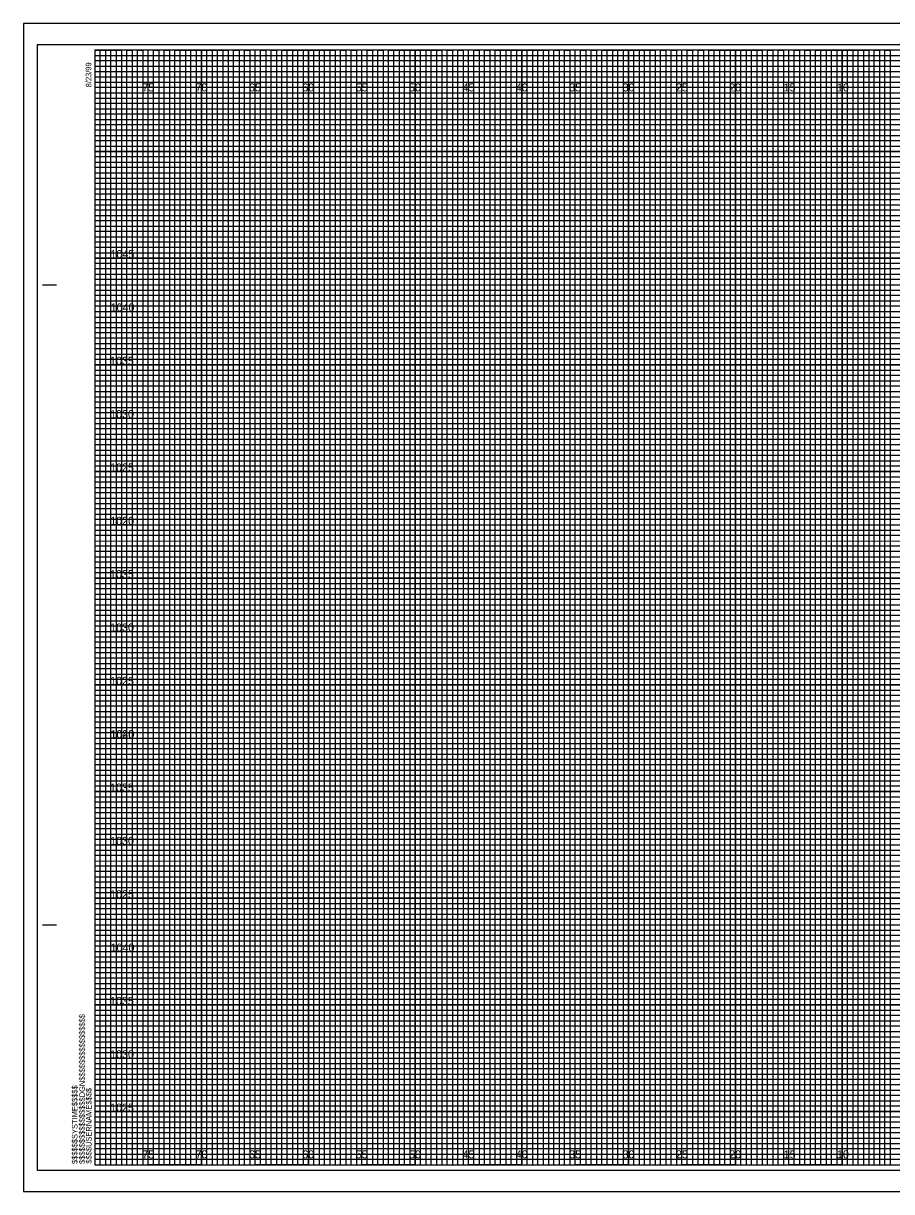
# Model space of a CAD drawing. Extents: x -7 to 162, y -2 to 987.
# Drawn here: x -6.7 to 74.6, y -2.5 to 107 of the extents above; entities that cross this region are included whole.
import ezdxf

# ---------------------------------------------------------------- set-up
doc = ezdxf.new("R2010")
doc.units = 0
for name, color, linetype in [('Exist Cross Section Cell', 7, 'Continuous'), ('Exist XS Center Line Elevation Label', 7, 'Continuous'), ('Exist XS Ground Line', 7, 'Continuous'), ('Prop CMT Concrete Structures', 7, 'Continuous'), ('Prop CMT Guardrail Widen Shoulder', 7, 'Continuous'), ('Prop CMT Pvmt Course 1', 7, 'Continuous'), ('Prop CMT Pvmt Surface', 7, 'Continuous'), ('Prop CMT Shld Paved Course 1', 7, 'Continuous'), ('Prop CMT Slope Grass', 7, 'Continuous'), ('Prop CMT Subgrade Earthwork', 7, 'Continuous'), ('Typical Text Label CELL', 7, 'Continuous')]:
    doc.layers.add(name, color=color, linetype=linetype)

msp = doc.modelspace()

# ---------------------------------------------------------------- linework, layer by layer
at = {"layer": 'Exist XS Center Line Elevation Label'}
for points in [[(0, 104.5), (2.5, 104.5), (2.5, 0), (7.5, 0), (7.5, 104.5), (12.5, 104.5), (12.5, 0), (17.5, 0), (17.5, 104.5), (22.5, 104.5), (22.5, 0), (27.5, 0), (27.5, 104.5), (32.5, 104.5), (32.5, 0), (37.5, 0), (37.5, 104.5), (42.5, 104.5), (42.5, 0), (47.5, 0), (47.5, 104.5), (52.5, 104.5), (52.5, 0), (57.5, 0), (57.5, 104.5), (62.5, 104.5), (62.5, 0), (67.5, 0), (67.5, 104.5), (72.5, 104.5), (72.5, 0), (77.5, 0)], [(0, 102), (137.5, 102)], [(0, 92.5), (160, 92.5), (160, 97.5), (0, 97.5)], [(0, 82.5), (160, 82.5), (160, 87.5), (0, 87.5)], [(0, 72.5), (160, 72.5), (160, 77.5), (0, 77.5)], [(0, 62.5), (160, 62.5), (160, 67.5), (0, 67.5)], [(0, 52.5), (160, 52.5), (160, 57.5), (0, 57.5)], [(0, 42.5), (160, 42.5), (160, 47.5), (0, 47.5)], [(0, 32.5), (160, 32.5), (160, 37.5), (0, 37.5)], [(0, 22.5), (160, 22.5), (160, 27.5), (0, 27.5)], [(0, 12.5), (160, 12.5), (160, 17.5), (0, 17.5)], [(0, 2.5), (160, 2.5), (160, 7.5), (0, 7.5)]]:
    msp.add_lwpolyline(points, dxfattribs=at)
at = {"layer": 'Exist XS Ground Line'}
for p, q in [((5, 104.5), (0, 104.5)), ((5, 0), (5, 104.5)), ((15, 104.5), (10, 104.5)), ((10, 104.5), (10, 0)), ((15, 0), (15, 104.5)), ((25, 104.5), (20, 104.5)), ((20, 104.5), (20, 0)), ((25, 0), (25, 104.5)), ((35, 104.5), (30, 104.5)), ((30, 104.5), (30, 0)), ((35, 0), (35, 104.5)), ((45, 104.5), (40, 104.5)), ((40, 104.5), (40, 0)), ((45, 0), (45, 104.5)), ((55, 104.5), (50, 104.5)), ((50, 104.5), (50, 0)), ((55, 0), (55, 104.5)), ((65, 104.5), (60, 104.5)), ((60, 104.5), (60, 0)), ((65, 0), (65, 104.5)), ((75, 104.5), (70, 104.5)), ((70, 104.5), (70, 0)), ((10, 0), (5, 0)), ((20, 0), (15, 0)), ((30, 0), (25, 0)), ((40, 0), (35, 0)), ((50, 0), (45, 0)), ((60, 0), (55, 0)), ((70, 0), (65, 0))]:
    msp.add_line(p, q, dxfattribs=at)
for points in [[(0, 100), (160, 100), (160, 95), (0, 95)], [(0, 90), (160, 90), (160, 85), (0, 85)], [(0, 80), (160, 80), (160, 75), (0, 75)], [(0, 70), (160, 70), (160, 65), (0, 65)], [(0, 60), (160, 60), (160, 55), (0, 55)], [(0, 50), (160, 50), (160, 45), (0, 45)], [(0, 40), (160, 40), (160, 35), (0, 35)], [(0, 30), (160, 30), (160, 25), (0, 25)], [(0, 20), (160, 20), (160, 15), (0, 15)], [(0, 10), (160, 10), (160, 5), (0, 5)]]:
    msp.add_lwpolyline(points, dxfattribs=at)
at = {"layer": 'Prop CMT Concrete Structures'}
for p, q in [((5, 0), (5, 104.5)), ((10, 0), (10, 104.5)), ((15, 0), (15, 104.5)), ((20, 0), (20, 104.5)), ((25, 0), (25, 104.5)), ((30, 0), (30, 104.5)), ((35, 0), (35, 104.5)), ((40, 0), (40, 104.5)), ((45, 0), (45, 104.5)), ((50, 0), (50, 104.5)), ((55, 0), (55, 104.5)), ((60, 0), (60, 104.5)), ((65, 0), (65, 104.5)), ((70, 0), (70, 104.5)), ((0, 100), (160, 100)), ((0, 95), (160, 95)), ((0, 90), (160, 90)), ((0, 85), (160, 85)), ((0, 80), (160, 80)), ((0, 75), (160, 75)), ((0, 70), (160, 70)), ((0, 65), (160, 65)), ((0, 60), (160, 60)), ((0, 55), (160, 55)), ((0, 50), (160, 50)), ((0, 45), (160, 45)), ((0, 40), (160, 40)), ((0, 35), (160, 35)), ((0, 30), (160, 30)), ((0, 25), (160, 25)), ((0, 20), (160, 20)), ((0, 15), (160, 15)), ((0, 10), (160, 10)), ((0, 5), (160, 5))]:
    msp.add_line(p, q, dxfattribs=at)
at = {"layer": 'Prop CMT Guardrail Widen Shoulder'}
for p, q in [((161.65, 107), (-6.7, 107)), ((-6.7, 107), (-6.7, -2.5)), ((-6.7, -2.5), (161.65, -2.5))]:
    msp.add_line(p, q, dxfattribs=at)
at = {"layer": 'Prop CMT Pvmt Course 1'}
msp.add_lwpolyline([(-6.7, -2.5), (161.65, -2.5), (161.65, 107), (-6.7, 107)], close=True, dxfattribs=at)
at = {"layer": 'Prop CMT Pvmt Surface'}
for points in [[(0, 0), (0.5, 0), (0.5, 104.5), (1, 104.5), (1, 0)], [(1, 0), (1.5, 0), (1.5, 104.5), (2, 104.5), (2, 0)], [(2.5, 0), (3, 0), (3, 104.5), (3.5, 104.5), (3.5, 0)], [(3.5, 0), (4, 0), (4, 104.5), (4.5, 104.5), (4.5, 0)], [(5, 0), (5.5, 0), (5.5, 104.5), (6, 104.5), (6, 0)], [(6, 0), (6.5, 0), (6.5, 104.5), (7, 104.5), (7, 0)], [(7.5, 0), (8, 0), (8, 104.5), (8.5, 104.5), (8.5, 0)], [(8.5, 0), (9, 0), (9, 104.5), (9.5, 104.5), (9.5, 0)], [(10, 0), (10.5, 0), (10.5, 104.5), (11, 104.5), (11, 0)], [(11, 0), (11.5, 0), (11.5, 104.5), (12, 104.5), (12, 0)], [(12.5, 0), (13, 0), (13, 104.5), (13.5, 104.5), (13.5, 0)], [(13.5, 0), (14, 0), (14, 104.5), (14.5, 104.5), (14.5, 0)], [(15, 0), (15.5, 0), (15.5, 104.5), (16, 104.5), (16, 0)], [(16, 0), (16.5, 0), (16.5, 104.5), (17, 104.5), (17, 0)], [(17.5, 0), (18, 0), (18, 104.5), (18.5, 104.5), (18.5, 0)], [(18.5, 0), (19, 0), (19, 104.5), (19.5, 104.5), (19.5, 0)], [(20, 0), (20.5, 0), (20.5, 104.5), (21, 104.5), (21, 0)], [(21, 0), (21.5, 0), (21.5, 104.5), (22, 104.5), (22, 0)], [(22.5, 0), (23, 0), (23, 104.5), (23.5, 104.5), (23.5, 0)], [(23.5, 0), (24, 0), (24, 104.5), (24.5, 104.5), (24.5, 0)], [(25, 0), (25.5, 0), (25.5, 104.5), (26, 104.5), (26, 0)], [(26, 0), (26.5, 0), (26.5, 104.5), (27, 104.5), (27, 0)], [(27.5, 0), (28, 0), (28, 104.5), (28.5, 104.5), (28.5, 0)], [(28.5, 0), (29, 0), (29, 104.5), (29.5, 104.5), (29.5, 0)], [(30, 0), (30.5, 0), (30.5, 104.5), (31, 104.5), (31, 0)], [(31, 0), (31.5, 0), (31.5, 104.5), (32, 104.5), (32, 0)], [(32.5, 0), (33, 0), (33, 104.5), (33.5, 104.5), (33.5, 0)], [(33.5, 0), (34, 0), (34, 104.5), (34.5, 104.5), (34.5, 0)], [(35, 0), (35.5, 0), (35.5, 104.5), (36, 104.5), (36, 0)], [(36, 0), (36.5, 0), (36.5, 104.5), (37, 104.5), (37, 0)], [(37.5, 0), (38, 0), (38, 104.5), (38.5, 104.5), (38.5, 0)], [(38.5, 0), (39, 0), (39, 104.5), (39.5, 104.5), (39.5, 0)], [(40, 0), (40.5, 0), (40.5, 104.5), (41, 104.5), (41, 0)], [(41, 0), (41.5, 0), (41.5, 104.5), (42, 104.5), (42, 0)], [(42.5, 0), (43, 0), (43, 104.5), (43.5, 104.5), (43.5, 0)], [(43.5, 0), (44, 0), (44, 104.5), (44.5, 104.5), (44.5, 0)], [(45, 0), (45.5, 0), (45.5, 104.5), (46, 104.5), (46, 0)], [(46, 0), (46.5, 0), (46.5, 104.5), (47, 104.5), (47, 0)], [(47.5, 0), (48, 0), (48, 104.5), (48.5, 104.5), (48.5, 0)], [(48.5, 0), (49, 0), (49, 104.5), (49.5, 104.5), (49.5, 0)], [(50, 0), (50.5, 0), (50.5, 104.5), (51, 104.5), (51, 0)], [(51, 0), (51.5, 0), (51.5, 104.5), (52, 104.5), (52, 0)], [(52.5, 0), (53, 0), (53, 104.5), (53.5, 104.5), (53.5, 0)], [(53.5, 0), (54, 0), (54, 104.5), (54.5, 104.5), (54.5, 0)], [(55, 0), (55.5, 0), (55.5, 104.5), (56, 104.5), (56, 0)], [(56, 0), (56.5, 0), (56.5, 104.5), (57, 104.5), (57, 0)], [(57.5, 0), (58, 0), (58, 104.5), (58.5, 104.5), (58.5, 0)], [(58.5, 0), (59, 0), (59, 104.5), (59.5, 104.5), (59.5, 0)], [(60, 0), (60.5, 0), (60.5, 104.5), (61, 104.5), (61, 0)], [(61, 0), (61.5, 0), (61.5, 104.5), (62, 104.5), (62, 0)], [(62.5, 0), (63, 0), (63, 104.5), (63.5, 104.5), (63.5, 0)], [(63.5, 0), (64, 0), (64, 104.5), (64.5, 104.5), (64.5, 0)], [(65, 0), (65.5, 0), (65.5, 104.5), (66, 104.5), (66, 0)], [(66, 0), (66.5, 0), (66.5, 104.5), (67, 104.5), (67, 0)], [(67.5, 0), (68, 0), (68, 104.5), (68.5, 104.5), (68.5, 0)], [(68.5, 0), (69, 0), (69, 104.5), (69.5, 104.5), (69.5, 0)], [(70, 0), (70.5, 0), (70.5, 104.5), (71, 104.5), (71, 0)], [(71, 0), (71.5, 0), (71.5, 104.5), (72, 104.5), (72, 0)], [(72.5, 0), (73, 0), (73, 104.5), (73.5, 104.5), (73.5, 0)], [(73.5, 0), (74, 0), (74, 104.5), (74.5, 104.5), (74.5, 0)]]:
    msp.add_lwpolyline(points, dxfattribs=at)
at = {"layer": 'Prop CMT Shld Paved Course 1'}
for p, q in [((0, 104), (130, 104)), ((130, 103.49), (0, 103.49)), ((0, 103.49), (0, 103)), ((0, 103), (130, 103)), ((130, 102.45), (0, 102.45)), ((0, 102.45), (0, 102)), ((0, 102), (160, 102))]:
    msp.add_line(p, q, dxfattribs=at)
for points in [[(0, 101.5), (135, 101.5), (160, 101.5), (160, 101), (0, 101)], [(0, 100.5), (160, 100.5), (160, 99.5), (0, 99.5)], [(0, 99), (160, 99), (160, 98.5), (0, 98.49)], [(0, 98), (160, 98), (160, 97), (0, 97)], [(0, 96.5), (160, 96.5), (160, 96), (0, 96)], [(0, 95.5), (160, 95.5), (160, 94.5), (0, 94.5)], [(0, 94), (160, 94), (160, 93.5), (0, 93.5)], [(0, 93), (160, 93), (160, 92), (0, 92)], [(0, 91.5), (160, 91.5), (160, 91), (0, 91)], [(0, 90.5), (160, 90.5), (160, 89.5), (0, 89.5)], [(0, 89), (160, 89), (160, 88.5), (0, 88.5)], [(0, 88), (160, 88), (160, 86.98), (160, 86.5), (160, 86), (0, 86)], [(0, 87), (160, 87), (160, 86.5), (0, 86.5)], [(0, 85.5), (160, 85.5), (160, 84.5), (0, 84.52)], [(0, 84.52), (160, 84.5), (160, 84), (0, 84)], [(0, 83.5), (160, 83.5), (160, 83), (0, 83)], [(0, 82), (160, 82), (160, 81.5), (0, 81.5)], [(0, 81), (160, 81), (160, 80.5), (0, 80.5)], [(-0.04, 79.45), (160, 79.45), (160, 78.94), (-0.04, 78.94)], [(0, 78.5), (160, 78.5), (160, 78), (0, 78)], [(0, 77), (160, 77), (160, 76.5), (0, 76.5)], [(0, 76), (160, 76), (160, 75.5), (0, 75.5)], [(0, 74.5), (160, 74.5), (160, 74), (0, 74)], [(0, 73.5), (160, 73.5), (160, 73), (0, 73)], [(0, 72), (160, 72), (160, 71.5), (0, 71.5)], [(0, 71), (160, 71), (160, 70.5), (0, 70.5)], [(0, 69.5), (160, 69.5), (160, 68.99), (0, 69)], [(0, 68.5), (160, 68.5), (160, 68), (0, 68)], [(0, 67), (160, 67), (160, 66.5), (0, 66.5)], [(0, 66), (160, 66), (160, 65.5), (0, 65.5)], [(0, 64.5), (160, 64.5), (160, 64), (0, 64)], [(0, 63.5), (160, 63.5), (160, 63), (0, 63)], [(0, 62), (160, 62), (160, 61.5), (0, 61.5)], [(0, 61), (160, 61), (160, 60.5), (0, 60.5)], [(0, 59.5), (160, 59.5), (160, 59), (0, 59)], [(0, 58.5), (160.03, 58.45), (160, 58), (0, 58)], [(0, 57), (160, 57), (160, 56.5), (0, 56.5)], [(0, 56), (160, 56), (160, 55.5), (0, 55.5)], [(0, 54.5), (160, 54.5), (160, 54), (0, 54)], [(0, 53.5), (160, 53.5), (160, 53), (0, 53)], [(0, 52), (160, 52), (160, 51.5), (0, 51.5)], [(0, 51), (160, 51), (160, 50.5), (0, 50.5)], [(0, 49.5), (160, 49.5), (160, 49), (0, 49)], [(0, 48.5), (160, 48.5), (160, 48), (0, 48)], [(0, 47), (160, 47), (160, 46.5), (0, 46.5)], [(0, 46), (160, 46), (160, 45.5), (0, 45.5)], [(0, 44.5), (160, 44.5), (160, 44), (0, 44)], [(0, 43.5), (160, 43.5), (160, 43), (0, 43)], [(0, 42), (160, 42), (160, 41.5), (0, 41.5)], [(0, 41), (160, 41), (160, 40.5), (0, 40.5)], [(0, 39.5), (160, 39.5), (160, 38.99), (0, 39)], [(0, 38.5), (160, 38.5), (160, 38), (0, 38)], [(0, 37), (160, 37), (160, 36.5), (0, 36.5)], [(0, 36), (160, 36), (160, 35.5), (0, 35.5)], [(0, 34.5), (160, 34.5), (160, 34), (0, 34)], [(0, 33.5), (160, 33.5), (160, 33), (0, 33)], [(0, 32), (160, 32), (160, 31.5), (0, 31.5)], [(0, 31), (160, 31), (160, 30.5), (0, 30.5)], [(0, 29.5), (160, 29.5), (160, 29), (0, 29)], [(0, 28.5), (160.03, 28.46), (160, 28), (0, 28)], [(0, 27), (160, 27), (160, 26.5), (0, 26.5)], [(0, 26), (160, 26), (160, 25.5), (0, 25.5)], [(0, 24.5), (160, 24.5), (160, 24), (0, 24)], [(0, 23.5), (160, 23.5), (160, 23), (0, 23)], [(0, 22), (160, 22), (160, 21.5), (0, 21.5)], [(0, 21), (160, 21), (160, 20.5), (0, 20.5)], [(0, 19.5), (160, 19.5), (160, 19), (0, 19)], [(0, 18.5), (160, 18.5), (160, 18), (0, 18)], [(0, 17), (160, 17), (160, 16.5), (0, 16.5)], [(0, 16), (160, 16), (160, 15.5), (0, 15.5)], [(0, 14.5), (160, 14.5), (160, 14), (0, 14)], [(0, 13.5), (160, 13.5), (160, 13), (0, 13)], [(0, 12), (160, 12), (160, 11.5), (0, 11.5)], [(0, 11), (160, 11), (160, 10.5), (0, 10.5)], [(0, 9.5), (160, 9.5), (160, 9), (0, 9)], [(0, 8.5), (160, 8.5), (160, 8), (0, 8)], [(0, 7), (160, 7), (160, 6.5), (0, 6.5)], [(0, 6), (160, 6), (160, 5.5), (0, 5.5)], [(0, 4.5), (160, 4.5), (160, 4), (0, 4)], [(0, 3.5), (160, 3.5), (160, 3), (0, 3)], [(0, 2), (160, 2), (160, 1.5), (0, 1.5)], [(0, 1), (160, 1), (160, 0.5), (0, 0.5)]]:
    msp.add_lwpolyline(points, dxfattribs=at)
at = {"layer": 'Prop CMT Slope Grass'}
msp.add_lwpolyline([(-5.4, -0.5), (161.2, -0.5), (161.2, 105), (-5.4, 105)], close=True, dxfattribs=at)
at = {"layer": 'Prop CMT Subgrade Earthwork'}
for p, q in [((-4.9, 82.5), (-3.65, 82.5)), ((-4.85, 82.5), (-3.6, 82.5)), ((-4.9, 22.5), (-3.65, 22.5)), ((-4.85, 22.5), (-3.6, 22.5)), ((0, 0), (0, 0)), ((0, 0), (0, 0)), ((0, 0), (0, 0)), ((0, 0), (0, 0)), ((0, 0), (0, 0)), ((0, 0), (0, 0)), ((0, 0), (0, 0))]:
    msp.add_line(p, q, dxfattribs=at)
msp.add_lwpolyline([(160, 104.5), (0, 104.5), (0, 0), (160, 0)], close=True, dxfattribs=at)

# ---------------------------------------------------------------- texts
at = {"layer": 'Exist Cross Section Cell'}
for s, p in [('75', (4.44, 100.62)), ('70', (9.43, 100.62)), ('65', (14.44, 100.62)), ('60', (19.43, 100.62)), ('55', (24.44, 100.62)), ('50', (29.43, 100.62)), ('45', (34.44, 100.62)), ('40', (39.43, 100.62)), ('35', (44.44, 100.62)), ('30', (49.43, 100.62)), ('25', (54.44, 100.62)), ('20', (59.43, 100.62)), ('15', (64.53, 100.62)), ('10', (69.52, 100.62)), ('75', (4.44, 0.62)), ('70', (9.43, 0.62)), ('65', (14.44, 0.62)), ('60', (19.43, 0.62)), ('55', (24.44, 0.62)), ('50', (29.43, 0.62)), ('45', (34.44, 0.62)), ('40', (39.43, 0.62)), ('35', (44.44, 0.62)), ('30', (49.43, 0.62)), ('25', (54.44, 0.62)), ('20', (59.43, 0.62)), ('15', (64.53, 0.62)), ('10', (69.52, 0.62))]:
    msp.add_text(s, height=0.75, dxfattribs=at).set_placement(p)
at = {"layer": 'Prop CMT Subgrade Earthwork'}
for s, p in [('8/23/99', (-0.33, 101)), ('$$$$$$$$$$$$$$$$DGN$$$$$$$$$$$$$$$$', (-0.94, 0.09)), ('$$$$$$SYSTIME$$$$$', (-1.63, 0.09)), ('$$$$USERNAME$$$$', (-0.31, 0.12))]:
    msp.add_text(s, height=0.525, rotation=90, dxfattribs=at).set_placement(p)
at = {"layer": 'Typical Text Label CELL'}
for s, p in [('1045', (1.46, 85)), ('1040', (1.47, 80)), ('1035', (1.42, 75)), ('1030', (1.43, 70)), ('1025', (1.43, 65)), ('1020', (1.44, 60)), ('1035', (1.42, 55)), ('1030', (1.43, 50)), ('1025', (1.43, 45)), ('1020', (1.44, 40)), ('1040', (1.47, 40)), ('1035', (1.42, 35)), ('1030', (1.43, 30)), ('1025', (1.43, 25)), ('1040', (1.47, 20)), ('1035', (1.42, 15)), ('1030', (1.43, 10)), ('1025', (1.43, 5))]:
    msp.add_text(s, height=0.75, dxfattribs=at).set_placement(p)

doc.saveas('drawing.dxf')
